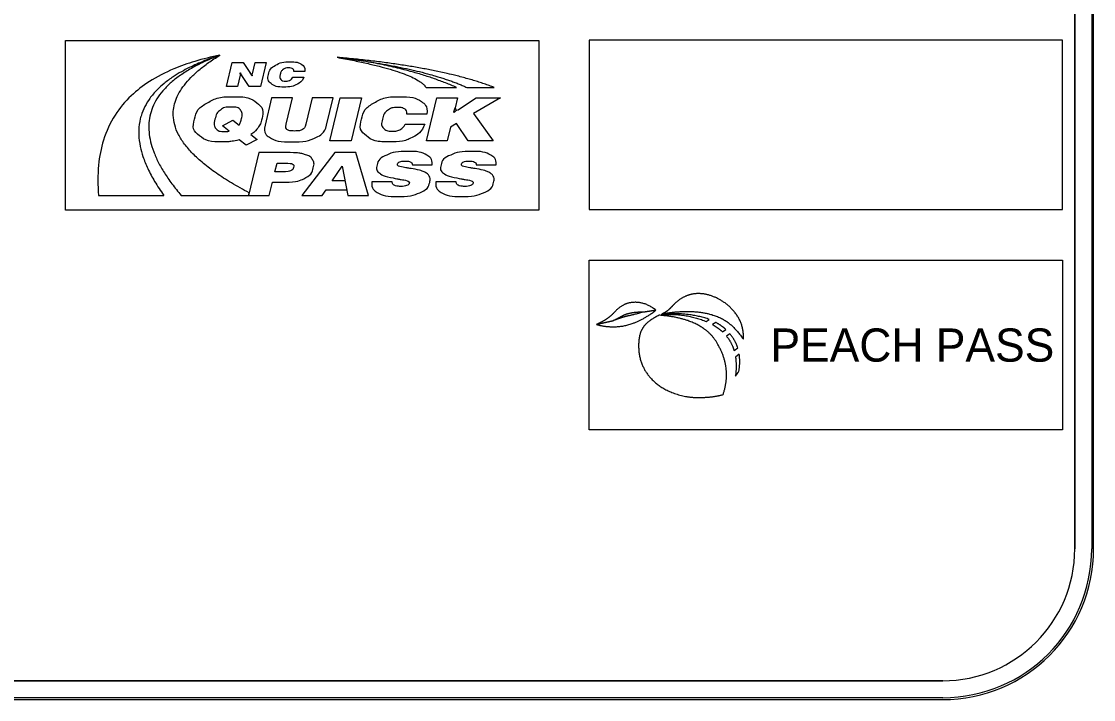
# Model space of a CAD drawing. Extents: x 17890459 to 17890580, y 17897938 to 17898017.
# Drawn here: x 17890554.22 to 17890561.33, y 17898002.1 to 17898006.6 of the extents above; entities that cross this region are included whole.
import ezdxf

# ---------------------------------------------------------------- set-up
doc = ezdxf.new("R2010")
doc.units = 0
for name, color, linetype in [('GSBWFill', 7, 'Continuous'), ('GSColorFill', 7, 'Continuous'), ('GSOutline', 7, 'Continuous'), ('ImageAttachment_dp', 7, 'Continuous'), ('Logo_dp', 7, 'Continuous')]:
    doc.layers.add(name, color=color, linetype=linetype)

msp = doc.modelspace()

# ---------------------------------------------------------------- linework, layer by layer
at = {"layer": 'GSBWFill'}
for p, q in [((17890561.2064, 17898010.0974), (17890561.2064, 17898003.0974)), ((17890561.3314, 17898003.0974), (17890561.3314, 17898010.0974)), ((17890560.3314, 17898002.2224), (17890551.8327, 17898002.2224)), ((17890551.8327, 17898002.0974), (17890560.3314, 17898002.0974))]:
    msp.add_line(p, q, dxfattribs=at)
for radius in [1, 0.875]:
    msp.add_arc((17890560.3314, 17898003.0974), radius, 270, 0, dxfattribs=at)
at = {"layer": 'GSColorFill'}
for p, q in [((17890561.2064, 17898010.0974), (17890561.2064, 17898003.0974)), ((17890561.3189, 17898010.0974), (17890561.3189, 17898003.0974)), ((17890561.3314, 17898003.0974), (17890561.3314, 17898010.0974)), ((17890561.3314, 17898003.0974), (17890561.3314, 17898010.0974)), ((17890561.3314, 17898003.0974), (17890561.3314, 17898010.0974)), ((17890560.3314, 17898002.2224), (17890551.8327, 17898002.2224)), ((17890551.8314, 17898002.0974), (17890560.3314, 17898002.0974)), ((17890560.3314, 17898002.1099), (17890551.8315, 17898002.1099)), ((17890551.8315, 17898002.0974), (17890560.3314, 17898002.0974)), ((17890551.8327, 17898002.0974), (17890560.3314, 17898002.0974))]:
    msp.add_line(p, q, dxfattribs=at)
msp.add_lwpolyline([(17890557.9848, 17898005.0123), (17890561.1253, 17898005.0123), (17890561.1253, 17898003.8873), (17890557.9848, 17898003.8873)], close=True, dxfattribs=at)
for radius in [1, 1, 0.875, 1, 0.9875]:
    msp.add_arc((17890560.3314, 17898003.0974), radius, 270, 0, dxfattribs=at)
at = {"layer": 'GSOutline'}
for p, q in [((17890561.2064, 17898003.0974), (17890561.2064, 17898010.0974)), ((17890561.3314, 17898003.0974), (17890561.3314, 17898010.0974)), ((17890551.8314, 17898002.2224), (17890560.3314, 17898002.2224)), ((17890551.8314, 17898002.0974), (17890560.3314, 17898002.0974))]:
    msp.add_line(p, q, dxfattribs=at)
for radius in [1, 0.875]:
    msp.add_arc((17890560.3314, 17898003.0974), radius, 270, 0, dxfattribs=at)
at = {"layer": 'ImageAttachment_dp'}
msp.add_lwpolyline([(17890557.9849, 17898005.3484), (17890561.1247, 17898005.3484), (17890561.1247, 17898006.4734), (17890557.9849, 17898006.4734)], close=True, dxfattribs=at)
at = {"layer": 'Logo_dp'}
for p, q in [((17890556.9024, 17898006.1593), (17890557.1044, 17898006.1593)), ((17890557.1732, 17898006.1593), (17890557.3545, 17898006.1593)), ((17890556.2969, 17898005.7274), (17890556.0775, 17898005.4433)), ((17890556.4368, 17898005.7274), (17890556.2969, 17898005.7274)), ((17890556.5201, 17898005.4433), (17890556.4368, 17898005.7274)), ((17890556.2796, 17898005.5402), (17890556.3463, 17898005.6378)), ((17890556.3463, 17898005.6378), (17890556.3831, 17898005.4433)), ((17890555.8627, 17898005.4433), (17890555.8835, 17898005.5304)), ((17890555.8835, 17898005.5304), (17890555.9661, 17898005.5304)), ((17890556.3648, 17898005.5402), (17890556.2796, 17898005.5402)), ((17890554.7297, 17898005.4433), (17890555.1626, 17898005.4433)), ((17890555.2776, 17898005.4433), (17890555.7245, 17898005.4433)), ((17890555.7245, 17898005.4433), (17890555.7285, 17898005.4599)), ((17890555.7245, 17898005.4433), (17890555.8627, 17898005.4433)), ((17890556.0775, 17898005.4433), (17890556.2134, 17898005.4433)), ((17890556.2134, 17898005.4433), (17890556.239, 17898005.4808)), ((17890556.239, 17898005.4808), (17890556.376, 17898005.4808)), ((17890556.3831, 17898005.4433), (17890556.5201, 17898005.4433)), ((17890558.3555, 17898004.67), (17890558.4281, 17898004.6807)), ((17890558.4281, 17898004.6807), (17890558.3555, 17898004.67)), ((17890558.4661, 17898004.6533), (17890558.4617, 17898004.6511)), ((17890558.0335, 17898004.5863), (17890558.1421, 17898004.611)), ((17890558.1421, 17898004.611), (17890558.0335, 17898004.5863)), ((17890558.7617, 17898004.6061), (17890558.7821, 17898004.6197)), ((17890558.8243, 17898004.6004), (17890558.8028, 17898004.5861)), ((17890558.8699, 17898004.5371), (17890558.8914, 17898004.5534)), ((17890558.9187, 17898004.5246), (17890558.8968, 17898004.508)), ((17890558.9464, 17898004.413), (17890558.9703, 17898004.4321)), ((17890558.9805, 17898004.3899), (17890558.956, 17898004.3698))]:
    msp.add_line(p, q, dxfattribs=at)
msp.add_lwpolyline([(17890554.5102, 17898006.4705), (17890557.6506, 17898006.4705), (17890557.6506, 17898005.3455), (17890554.5102, 17898005.3455)], close=True, dxfattribs=at)
for points in [[(17890555.5777, 17898006.1666), (17890555.6156, 17898006.3248), (17890555.6886, 17898006.3248), (17890555.7382, 17898006.2513)], [(17890555.7503, 17898006.2501), (17890555.7682, 17898006.3248), (17890555.8412, 17898006.3248), (17890555.8033, 17898006.1666), (17890555.73, 17898006.1666), (17890555.6803, 17898006.2396)], [(17890555.6685, 17898006.2407), (17890555.6507, 17898006.1666), (17890555.5777, 17898006.1666)], [(17890556.0189, 17898006.228), (17890556.0917, 17898006.228)], [(17890556.0992, 17898006.265), (17890556.0256, 17898006.265)], [(17890555.8779, 17898006.0902), (17890555.8342, 17898005.908)], [(17890555.9741, 17898005.9151), (17890556.016, 17898006.0902), (17890555.8779, 17898006.0902)], [(17890556.2424, 17898005.908), (17890556.2861, 17898006.0902), (17890556.1479, 17898006.0902), (17890556.106, 17898005.9151)], [(17890556.2652, 17898005.8061), (17890556.3333, 17898006.0902), (17890556.4742, 17898006.0902), (17890556.4062, 17898005.8061), (17890556.2652, 17898005.8061)], [(17890556.9066, 17898005.8061), (17890556.9746, 17898006.0902), (17890557.1117, 17898006.0902), (17890557.0957, 17898006.0232)], [(17890557.1105, 17898006.0095), (17890557.2355, 17898006.0902), (17890557.3958, 17898006.0902), (17890557.2171, 17898005.9854), (17890557.3477, 17898005.8061), (17890557.183, 17898005.8061), (17890557.1051, 17898005.9198), (17890557.0653, 17898005.8965), (17890557.0437, 17898005.8061), (17890556.9066, 17898005.8061)], [(17890556.9078, 17898005.9828), (17890556.7756, 17898005.9828)], [(17890555.596, 17898005.8687), (17890555.5526, 17898005.9054), (17890555.6202, 17898005.9429), (17890555.6623, 17898005.9088)], [(17890556.7635, 17898005.9163), (17890556.8943, 17898005.9163)], [(17890555.7411, 17898005.8478), (17890555.7811, 17898005.8149), (17890555.7083, 17898005.7753)], [(17890555.7083, 17898005.7753), (17890555.6637, 17898005.8126)], [(17890555.9695, 17898005.7274), (17890555.7925, 17898005.7274), (17890555.7245, 17898005.4433)], [(17890555.9001, 17898005.5998), (17890555.914, 17898005.6577), (17890555.9584, 17898005.6577)], [(17890556.812, 17898005.6456), (17890556.9432, 17898005.6456)], [(17890557.2362, 17898005.6456), (17890557.3674, 17898005.6456)], [(17890555.9445, 17898005.5998), (17890555.9001, 17898005.5998)], [(17890556.6778, 17898005.532), (17890556.5432, 17898005.532)], [(17890557.102, 17898005.532), (17890556.9674, 17898005.532)]]:
    msp.add_lwpolyline(points, dxfattribs=at)
for centre, radius, start, end in [((17890555.8868, 17898004.5928), 1.8149, 101.22741, 106.6089), ((17890556.0467, 17898004.8046), 1.6501, 110.40371, 112.19847), ((17890556.1271, 17898004.588), 1.8811, 108.3962, 110.39851), ((17890555.6342, 17898005.3054), 1.0577, 112.53473, 122.41454), ((17890555.7671, 17898004.9924), 1.3978, 106.58875, 112.64968), ((17890555.8214, 17898005.3054), 1.1007, 116.43907, 119.48622), ((17890555.9039, 17898005.1397), 1.2857, 113.93205, 116.4404), ((17890555.9786, 17898004.972), 1.4693, 112.20568, 113.94158), ((17890555.5042, 17898005.5123), 0.8134, 122.49628, 133.27108), ((17890555.6352, 17898005.6093), 0.744, 123.52381, 129.27617), ((17890555.731, 17898005.465), 0.9173, 119.47681, 123.53572), ((17890555.4639, 17898005.8009), 0.4867, 135.31075, 144.06718), ((17890555.5428, 17898005.7233), 0.5973, 129.33266, 135.33724), ((17890555.4211, 17898005.6015), 0.6914, 133.32357, 147.26107), ((17890555.4027, 17898005.8459), 0.4107, 144.14252, 152.82845), ((17890555.3691, 17898005.8634), 0.3728, 152.85681, 163.59143), ((17890555.4163, 17898005.607), 0.6845, 147.43247, 162.77657), ((17890555.3693, 17898005.8639), 0.3729, 163.67802, 175.10581), ((17890555.4008, 17898005.8611), 0.4045, 175.09873, 182.16092), ((17890555.4719, 17898005.8651), 0.4757, 182.31054, 191.89985), ((17890555.5343, 17898005.5704), 0.808, 162.77657, 174.76818), ((17890555.5793, 17898005.8875), 0.5853, 191.87764, 198.62904), ((17890555.7398, 17898005.9424), 0.755, 198.68546, 205.21399), ((17890555.8224, 17898005.544), 1.0973, 174.76818, 185.26721), ((17890555.9494, 17898006.0416), 0.9869, 205.24031, 210.82785), ((17890556.2284, 17898006.2078), 1.3117, 210.8164, 215.64808), ((17890558.3502, 17898004.6962), 0.7559, 323.22177, 326.19817)]:
    msp.add_arc(centre, radius, start, end, dxfattribs=at)
for points, degree in [([(17890555.5334, 17898006.373), (17890554.7459, 17898006.0703), (17890555.2776, 17898005.4433)], 2), ([(17890555.7285, 17898005.4599), (17890554.8314, 17898005.937), (17890555.5334, 17898006.373)], 2), ([(17890557.1044, 17898006.1593), (17890556.779, 17898006.3017), (17890556.3122, 17898006.3594)], 2), ([(17890556.3122, 17898006.3594), (17890556.8394, 17898006.263), (17890556.9024, 17898006.1593)], 2), ([(17890557.3545, 17898006.1593), (17890556.9983, 17898006.2974), (17890556.3122, 17898006.3594)], 2), ([(17890556.3122, 17898006.3594), (17890556.8912, 17898006.2891), (17890557.1732, 17898006.1593)], 2), ([(17890556.0917, 17898006.228), (17890556.0814, 17898006.1969), (17890556.0469, 17898006.1796), (17890556.0125, 17898006.1622), (17890555.9611, 17898006.1622), (17890555.9035, 17898006.1622), (17890555.8758, 17898006.1845), (17890555.8481, 17898006.2068), (17890555.8574, 17898006.2456), (17890555.8667, 17898006.2843), (17890555.9047, 17898006.3066), (17890555.9428, 17898006.329), (17890555.9992, 17898006.329), (17890556.0513, 17898006.329), (17890556.0773, 17898006.3123), (17890556.1033, 17898006.2957), (17890556.0992, 17898006.265)], 3), ([(17890556.0256, 17898006.265), (17890556.0269, 17898006.2771), (17890556.0181, 17898006.2832), (17890556.0093, 17898006.2894), (17890555.9907, 17898006.2894), (17890555.9681, 17898006.2894), (17890555.9542, 17898006.2785), (17890555.9402, 17898006.2676), (17890555.935, 17898006.2455), (17890555.9298, 17898006.2239), (17890555.9392, 17898006.2129), (17890555.9486, 17898006.2018), (17890555.9719, 17898006.2018), (17890555.9896, 17898006.2018), (17890556.0019, 17898006.2086), (17890556.0141, 17898006.2155), (17890556.0189, 17898006.228)], 3), ([(17890555.6803, 17898006.2396), (17890555.6778, 17898006.243), (17890555.6751, 17898006.2481), (17890555.6723, 17898006.2531), (17890555.6695, 17898006.2592), (17890555.6698, 17898006.2535), (17890555.6695, 17898006.2488), (17890555.6693, 17898006.2441), (17890555.6685, 17898006.2407)], 3), ([(17890555.7382, 17898006.2513), (17890555.7385, 17898006.2508), (17890555.739, 17898006.25), (17890555.7447, 17898006.2411), (17890555.7485, 17898006.2335), (17890555.7484, 17898006.2378), (17890555.7489, 17898006.242), (17890555.7493, 17898006.2463), (17890555.7503, 17898006.2501)], 3), ([(17890555.6637, 17898005.8126), (17890555.6403, 17898005.8052), (17890555.6137, 17898005.8017), (17890555.5872, 17898005.7983), (17890555.5538, 17898005.7983), (17890555.4501, 17898005.7983), (17890555.3997, 17898005.8386), (17890555.3493, 17898005.8789), (17890555.3658, 17898005.9479), (17890555.3825, 17898006.0174), (17890555.4521, 17898006.0575), (17890555.5218, 17898006.0976), (17890555.6255, 17898006.0976), (17890555.729, 17898006.0976), (17890555.7793, 17898006.0575), (17890555.8296, 17898006.0174), (17890555.813, 17898005.948), (17890555.8055, 17898005.9168), (17890555.7876, 17898005.892), (17890555.7697, 17898005.8673), (17890555.7411, 17898005.8478)], 3), ([(17890556.8943, 17898005.9163), (17890556.8757, 17898005.8606), (17890556.8139, 17898005.8294), (17890556.7521, 17898005.7983), (17890556.6598, 17898005.7983), (17890556.5564, 17898005.7983), (17890556.5067, 17898005.8383), (17890556.457, 17898005.8783), (17890556.4737, 17898005.9479), (17890556.4903, 17898006.0174), (17890556.5586, 17898006.0575), (17890556.6269, 17898006.0976), (17890556.7283, 17898006.0976), (17890556.8217, 17898006.0976), (17890556.8684, 17898006.0677), (17890556.9151, 17898006.0379), (17890556.9078, 17898005.9828)], 3), ([(17890555.6623, 17898005.9088), (17890555.667, 17898005.9162), (17890555.6705, 17898005.9253), (17890555.674, 17898005.9345), (17890555.6773, 17898005.948), (17890555.6874, 17898005.9902), (17890555.6708, 17898006.0097), (17890555.6543, 17898006.0293), (17890555.6092, 17898006.0293), (17890555.5642, 17898006.0293), (17890555.5383, 17898006.0096), (17890555.5123, 17898005.99), (17890555.5023, 17898005.948), (17890555.4923, 17898005.9065), (17890555.5085, 17898005.8868), (17890555.5247, 17898005.867), (17890555.5692, 17898005.867), (17890555.5765, 17898005.867), (17890555.583, 17898005.8674), (17890555.5896, 17898005.8678), (17890555.596, 17898005.8687)], 3), ([(17890556.7756, 17898005.9828), (17890556.7779, 17898006.0044), (17890556.7621, 17898006.0155), (17890556.7463, 17898006.0265), (17890556.713, 17898006.0265), (17890556.6724, 17898006.0265), (17890556.6474, 17898006.0069), (17890556.6224, 17898005.9874), (17890556.6129, 17898005.9478), (17890556.6036, 17898005.9091), (17890556.6205, 17898005.8892), (17890556.6374, 17898005.8693), (17890556.6792, 17898005.8693), (17890556.711, 17898005.8693), (17890556.733, 17898005.8816), (17890556.7549, 17898005.8939), (17890556.7635, 17898005.9163)], 3), ([(17890557.0957, 17898006.0232), (17890557.0953, 17898006.0216), (17890557.0909, 17898006.0082), (17890557.0874, 17898005.9981), (17890557.0853, 17898005.9918), (17890557.0952, 17898005.9991), (17890557.1004, 17898006.0028), (17890557.1057, 17898006.0064), (17890557.1105, 17898006.0095)], 3), ([(17890556.106, 17898005.9151), (17890556.1, 17898005.8903), (17890556.0826, 17898005.8803), (17890556.0651, 17898005.8703), (17890556.03, 17898005.8703), (17890555.9941, 17898005.8703), (17890555.9811, 17898005.8804), (17890555.9682, 17898005.8905), (17890555.9741, 17898005.9151)], 3), ([(17890555.8342, 17898005.908), (17890555.8215, 17898005.8548), (17890555.8673, 17898005.8265), (17890555.9131, 17898005.7983), (17890556.0128, 17898005.7983), (17890556.1118, 17898005.7983), (17890556.1708, 17898005.8265), (17890556.2297, 17898005.8548), (17890556.2424, 17898005.908)], 3), ([(17890555.9661, 17898005.5304), (17890556.0468, 17898005.5304), (17890556.0953, 17898005.5556), (17890556.1439, 17898005.5809), (17890556.1553, 17898005.6287), (17890556.1626, 17898005.6589), (17890556.1489, 17898005.6806), (17890556.1353, 17898005.7023), (17890556.1015, 17898005.7139), (17890556.081, 17898005.721), (17890556.0514, 17898005.7242), (17890556.0218, 17898005.7274), (17890555.9695, 17898005.7274)], 3), ([(17890556.9432, 17898005.6456), (17890556.9473, 17898005.6885), (17890556.9051, 17898005.7116), (17890556.8629, 17898005.7348), (17890556.7803, 17898005.7348), (17890556.6959, 17898005.7348), (17890556.6419, 17898005.7106), (17890556.5879, 17898005.6864), (17890556.5778, 17898005.6444), (17890556.5695, 17898005.6095), (17890556.595, 17898005.5899), (17890556.6206, 17898005.5703), (17890556.7117, 17898005.5532), (17890556.722, 17898005.5512), (17890556.7399, 17898005.5482), (17890556.7949, 17898005.5387), (17890556.7913, 17898005.5237), (17890556.7889, 17898005.514), (17890556.7739, 17898005.5085), (17890556.7589, 17898005.503), (17890556.7344, 17898005.503), (17890556.7056, 17898005.503), (17890556.6926, 17898005.5098), (17890556.6796, 17898005.5165), (17890556.6778, 17898005.532)], 3), ([(17890557.3674, 17898005.6456), (17890557.3715, 17898005.6885), (17890557.3293, 17898005.7116), (17890557.2871, 17898005.7348), (17890557.2044, 17898005.7348), (17890557.12, 17898005.7348), (17890557.0661, 17898005.7106), (17890557.0121, 17898005.6864), (17890557.002, 17898005.6444), (17890556.9937, 17898005.6095), (17890557.0192, 17898005.5899), (17890557.0447, 17898005.5703), (17890557.1358, 17898005.5532), (17890557.1462, 17898005.5512), (17890557.1641, 17898005.5482), (17890557.219, 17898005.5387), (17890557.2154, 17898005.5237), (17890557.2131, 17898005.514), (17890557.1981, 17898005.5085), (17890557.1831, 17898005.503), (17890557.1586, 17898005.503), (17890557.1297, 17898005.503), (17890557.1168, 17898005.5098), (17890557.1038, 17898005.5165), (17890557.102, 17898005.532)], 3), ([(17890555.9584, 17898005.6577), (17890556.0033, 17898005.6577), (17890556.0155, 17898005.6511), (17890556.0276, 17898005.6446), (17890556.0238, 17898005.6286), (17890556.0199, 17898005.6125), (17890556.0041, 17898005.6061), (17890555.9883, 17898005.5998), (17890555.9445, 17898005.5998)], 3), ([(17890556.5432, 17898005.532), (17890556.5381, 17898005.4862), (17890556.5824, 17898005.4608), (17890556.6267, 17898005.4354), (17890556.712, 17898005.4354), (17890556.8048, 17898005.4354), (17890556.8607, 17898005.4608), (17890556.9166, 17898005.4862), (17890556.9278, 17898005.533), (17890556.9331, 17898005.555), (17890556.9235, 17898005.5713), (17890556.914, 17898005.5876), (17890556.8888, 17898005.5994), (17890556.8665, 17898005.61), (17890556.7942, 17898005.6223), (17890556.7799, 17898005.6248), (17890556.7723, 17898005.6262), (17890556.7709, 17898005.6264), (17890556.7679, 17898005.627), (17890556.7107, 17898005.6366), (17890556.7141, 17898005.6511), (17890556.7165, 17898005.661), (17890556.7284, 17898005.6658), (17890556.7404, 17898005.6706), (17890556.7626, 17898005.6706), (17890556.7877, 17898005.6706), (17890556.7997, 17898005.6644), (17890556.8118, 17898005.6582), (17890556.812, 17898005.6456)], 3), ([(17890556.9674, 17898005.532), (17890556.9623, 17898005.4862), (17890557.0066, 17898005.4608), (17890557.0509, 17898005.4354), (17890557.1361, 17898005.4354), (17890557.229, 17898005.4354), (17890557.2849, 17898005.4608), (17890557.3408, 17898005.4862), (17890557.352, 17898005.533), (17890557.3572, 17898005.555), (17890557.3477, 17898005.5713), (17890557.3382, 17898005.5876), (17890557.313, 17898005.5994), (17890557.2907, 17898005.61), (17890557.2184, 17898005.6223), (17890557.2041, 17898005.6248), (17890557.1965, 17898005.6262), (17890557.1951, 17898005.6264), (17890557.192, 17898005.627), (17890557.1348, 17898005.6366), (17890557.1383, 17898005.6511), (17890557.1407, 17898005.661), (17890557.1526, 17898005.6658), (17890557.1646, 17898005.6706), (17890557.1867, 17898005.6706), (17890557.2118, 17898005.6706), (17890557.2239, 17898005.6644), (17890557.236, 17898005.6582), (17890557.2362, 17898005.6456)], 3), ([(17890558.6606, 17898004.7858), (17890558.5977, 17898004.7703), (17890558.5474, 17898004.7193)], 2), ([(17890558.8057, 17898004.7727), (17890558.7298, 17898004.8016), (17890558.6606, 17898004.7858)], 2), ([(17890558.9498, 17898004.6683), (17890558.8896, 17898004.7413), (17890558.8057, 17898004.7727)], 2), ([(17890558.259, 17898004.7306), (17890558.2031, 17898004.7226), (17890558.1529, 17898004.6683)], 2), ([(17890558.4281, 17898004.6807), (17890558.3467, 17898004.7458), (17890558.259, 17898004.7306)], 2), ([(17890558.5474, 17898004.7193), (17890558.5272, 17898004.6983), (17890558.5186, 17898004.69)], 2), ([(17890558.1529, 17898004.6683), (17890558.1291, 17898004.6413), (17890558.1038, 17898004.6249)], 2), ([(17890558.1421, 17898004.611), (17890558.1647, 17898004.6217), (17890558.2043, 17898004.6436)], 2), ([(17890558.1671, 17898004.5716), (17890558.2935, 17898004.5782), (17890558.4281, 17898004.6807)], 2), ([(17890558.2416, 17898004.6427), (17890558.2198, 17898004.6383), (17890558.1884, 17898004.6272)], 2), ([(17890558.2043, 17898004.6436), (17890558.2279, 17898004.6585), (17890558.2743, 17898004.6655)], 2), ([(17890558.3555, 17898004.67), (17890558.2613, 17898004.6471), (17890558.2416, 17898004.6427)], 2), ([(17890558.2743, 17898004.6655), (17890558.306, 17898004.6709), (17890558.3555, 17898004.67)], 2), ([(17890558.4495, 17898004.6477), (17890558.3674, 17898004.6078), (17890558.3426, 17898004.5655)], 2), ([(17890558.7431, 17898004.5605), (17890558.6338, 17898004.6349), (17890558.4495, 17898004.6477)], 2), ([(17890558.4617, 17898004.6511), (17890558.6265, 17898004.6633), (17890558.7617, 17898004.6061)], 2), ([(17890558.7821, 17898004.6197), (17890558.646, 17898004.6693), (17890558.4661, 17898004.6533)], 2), ([(17890558.4673, 17898004.6565), (17890558.5175, 17898004.6665), (17890558.5741, 17898004.6709)], 2), ([(17890558.4908, 17898004.6679), (17890558.4904, 17898004.6675), (17890558.4673, 17898004.6565)], 2), ([(17890558.5186, 17898004.69), (17890558.5042, 17898004.6754), (17890558.4908, 17898004.6679)], 2), ([(17890558.5741, 17898004.6709), (17890558.7765, 17898004.6852), (17890558.8937, 17898004.6081)], 2), ([(17890559.0082, 17898004.4888), (17890559.0143, 17898004.5882), (17890558.9498, 17898004.6683)], 2), ([(17890558.1038, 17898004.6249), (17890558.0742, 17898004.6048), (17890558.0335, 17898004.5863)], 2), ([(17890558.0335, 17898004.5863), (17890558.0962, 17898004.5681), (17890558.1671, 17898004.5716)], 2), ([(17890558.1884, 17898004.6272), (17890558.1717, 17898004.6219), (17890558.1421, 17898004.611)], 2), ([(17890558.3426, 17898004.5655), (17890558.3069, 17898004.5164), (17890558.3145, 17898004.4094)], 2), ([(17890558.8396, 17898004.4525), (17890558.8019, 17898004.5223), (17890558.7431, 17898004.5605)], 2), ([(17890558.8028, 17898004.5861), (17890558.8401, 17898004.5647), (17890558.8699, 17898004.5371)], 2), ([(17890558.8914, 17898004.5534), (17890558.8667, 17898004.5768), (17890558.8243, 17898004.6004)], 2), ([(17890558.8937, 17898004.6081), (17890558.9445, 17898004.5766), (17890559.0082, 17898004.4888)], 2), ([(17890558.8968, 17898004.508), (17890558.931, 17898004.467), (17890558.9464, 17898004.413)], 2), ([(17890558.9703, 17898004.4321), (17890558.9549, 17898004.4814), (17890558.9187, 17898004.5246)], 2), ([(17890558.8735, 17898004.1213), (17890558.9321, 17898004.2923), (17890558.8396, 17898004.4525)], 2), ([(17890558.3145, 17898004.4094), (17890558.3262, 17898004.3027), (17890558.3938, 17898004.2303)], 2), ([(17890558.956, 17898004.3698), (17890558.9639, 17898004.3062), (17890558.9556, 17898004.2436)], 2), ([(17890558.9783, 17898004.2757), (17890558.9884, 17898004.3357), (17890558.9805, 17898004.3899)], 2), ([(17890558.3938, 17898004.2303), (17890558.4802, 17898004.1369), (17890558.6251, 17898004.109)], 2), ([(17890558.6251, 17898004.109), (17890558.6795, 17898004.0983), (17890558.7577, 17898004.1032)], 2), ([(17890558.7577, 17898004.1032), (17890558.8217, 17898004.1066), (17890558.8735, 17898004.1213)], 2)]:
    msp.add_open_spline(points, degree=degree, dxfattribs=at)

# ---------------------------------------------------------------- texts
at = {"layer": 'GSColorFill'}
msp.add_text('PEACH PASS', height=0.22032, dxfattribs=at).set_placement((17890559.1879, 17898004.3396))

doc.saveas('drawing.dxf')
